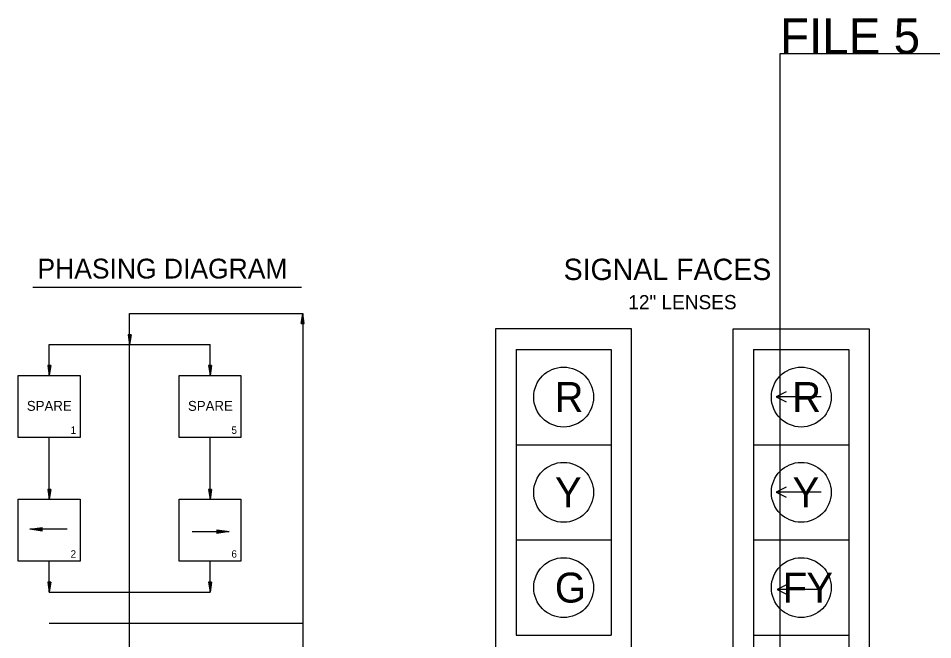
# Model space of a CAD drawing. Extents: x -218554 to 420114, y -565956 to -483460.
# Drawn here: x 418454.1 to 418625.5, y -565580 to -565463.6 of the extents above; entities that cross this region are included whole.
import ezdxf

# ---------------------------------------------------------------- set-up
doc = ezdxf.new("R2010")
doc.units = 0
for name, color, linetype in [('Level 57', 7, 'Continuous'), ('Level 61', 7, 'Continuous'), ('Template', 7, 'Continuous')]:
    doc.layers.add(name, color=color, linetype=linetype)

msp = doc.modelspace()

# ---------------------------------------------------------------- linework, layer by layer
at = {"layer": 'Level 57'}
for p, q in [((418456.77, -565513.98), (418507.17, -565513.98)), ((418474.94, -565640.7), (418474.94, -565518.95)), ((418474.94, -565518.95), (418507.41, -565518.95)), ((418507.13, -565520.81), (418507.41, -565518.95)), ((418507.18, -565520.81), (418507.41, -565519.26)), ((418507.41, -565518.95), (418507.41, -565640.7)), ((418507.69, -565520.81), (418507.41, -565518.95)), ((418507.64, -565520.81), (418507.41, -565519.26)), ((418507.13, -565520.81), (418507.69, -565520.81)), ((418507.23, -565520.81), (418507.41, -565519.58)), ((418507.27, -565520.81), (418507.41, -565519.89)), ((418507.32, -565520.81), (418507.41, -565520.21)), ((418507.37, -565520.81), (418507.41, -565520.52)), ((418507.59, -565520.81), (418507.41, -565519.58)), ((418507.55, -565520.81), (418507.41, -565519.89)), ((418507.5, -565520.81), (418507.41, -565520.21)), ((418507.45, -565520.81), (418507.41, -565520.52)), ((418474.67, -565522.9), (418474.94, -565524.75)), ((418475.22, -565522.9), (418474.67, -565522.9)), ((418474.71, -565522.9), (418474.94, -565524.44)), ((418474.76, -565522.9), (418474.94, -565524.12)), ((418474.81, -565522.9), (418474.94, -565523.81)), ((418474.85, -565522.9), (418474.94, -565523.5)), ((418474.9, -565522.9), (418474.94, -565523.19)), ((418475.22, -565522.9), (418474.94, -565524.75)), ((418475.03, -565522.9), (418474.94, -565523.5)), ((418475.13, -565522.9), (418474.94, -565524.12)), ((418475.18, -565522.9), (418474.94, -565524.44)), ((418475.08, -565522.9), (418474.94, -565523.81)), ((418474.99, -565522.9), (418474.94, -565523.19)), ((418459.87, -565530.55), (418459.87, -565524.75)), ((418459.87, -565524.75), (418490.02, -565524.75)), ((418490.02, -565530.55), (418490.02, -565524.75)), ((418459.59, -565528.69), (418459.87, -565530.55)), ((418460.15, -565528.69), (418459.59, -565528.69)), ((418459.64, -565528.69), (418459.87, -565530.24)), ((418459.69, -565528.69), (418459.87, -565529.92)), ((418459.73, -565528.69), (418459.87, -565529.61)), ((418459.78, -565528.69), (418459.87, -565529.3)), ((418459.83, -565528.69), (418459.87, -565528.99)), ((418460.15, -565528.69), (418459.87, -565530.55)), ((418459.96, -565528.69), (418459.87, -565529.3)), ((418460.05, -565528.69), (418459.87, -565529.92)), ((418460.1, -565528.69), (418459.87, -565530.24)), ((418460.01, -565528.69), (418459.87, -565529.61)), ((418459.91, -565528.69), (418459.87, -565528.99)), ((418489.74, -565528.69), (418490.02, -565530.55)), ((418490.3, -565528.69), (418489.74, -565528.69)), ((418489.79, -565528.69), (418490.02, -565530.24)), ((418489.83, -565528.69), (418490.02, -565529.92)), ((418489.88, -565528.69), (418490.02, -565529.61)), ((418489.93, -565528.69), (418490.02, -565529.3)), ((418489.97, -565528.69), (418490.02, -565528.99)), ((418490.3, -565528.69), (418490.02, -565530.55)), ((418490.11, -565528.69), (418490.02, -565529.3)), ((418490.2, -565528.69), (418490.02, -565529.92)), ((418490.25, -565528.69), (418490.02, -565530.24)), ((418490.16, -565528.69), (418490.02, -565529.61)), ((418490.06, -565528.69), (418490.02, -565528.99)), ((418459.87, -565553.74), (418459.87, -565542.14)), ((418490.02, -565553.74), (418490.02, -565542.14)), ((418459.59, -565551.88), (418459.87, -565553.74)), ((418460.15, -565551.88), (418459.59, -565551.88)), ((418459.64, -565551.88), (418459.87, -565553.43)), ((418459.69, -565551.88), (418459.87, -565553.11)), ((418459.73, -565551.88), (418459.87, -565552.8)), ((418459.78, -565551.88), (418459.87, -565552.49)), ((418459.83, -565551.88), (418459.87, -565552.18)), ((418460.15, -565551.88), (418459.87, -565553.74)), ((418459.96, -565551.88), (418459.87, -565552.49)), ((418460.05, -565551.88), (418459.87, -565553.11)), ((418460.1, -565551.88), (418459.87, -565553.43)), ((418460.01, -565551.88), (418459.87, -565552.8)), ((418459.91, -565551.88), (418459.87, -565552.18)), ((418489.74, -565551.88), (418490.02, -565553.74)), ((418490.3, -565551.88), (418489.74, -565551.88)), ((418489.79, -565551.88), (418490.02, -565553.43)), ((418489.83, -565551.88), (418490.02, -565553.11)), ((418489.88, -565551.88), (418490.02, -565552.8)), ((418489.93, -565551.88), (418490.02, -565552.49)), ((418489.97, -565551.88), (418490.02, -565552.18)), ((418490.3, -565551.88), (418490.02, -565553.74)), ((418490.11, -565551.88), (418490.02, -565552.49)), ((418490.2, -565551.88), (418490.02, -565553.11)), ((418490.25, -565551.88), (418490.02, -565553.43)), ((418490.16, -565551.88), (418490.02, -565552.8)), ((418490.06, -565551.88), (418490.02, -565552.18)), ((418456.26, -565559.36), (418458.58, -565559.01)), ((418463.22, -565559.36), (418456.26, -565559.36)), ((418458.58, -565559.71), (418456.26, -565559.36)), ((418458.58, -565559.07), (418456.65, -565559.36)), ((418456.65, -565559.36), (418458.58, -565559.65)), ((418457.05, -565559.36), (418458.58, -565559.13)), ((418458.58, -565559.59), (418457.05, -565559.36)), ((418458.58, -565559.19), (418457.43, -565559.36)), ((418457.43, -565559.36), (418458.58, -565559.53)), ((418457.83, -565559.36), (418458.58, -565559.25)), ((418458.58, -565559.47), (418457.83, -565559.36)), ((418458.58, -565559.3), (418458.21, -565559.36)), ((418458.21, -565559.36), (418458.58, -565559.41)), ((418458.58, -565559.71), (418458.58, -565559.01)), ((418486.64, -565559.78), (418493.6, -565559.78)), ((418491.28, -565559.43), (418493.6, -565559.78)), ((418491.28, -565559.43), (418491.28, -565560.13)), ((418493.21, -565559.78), (418491.28, -565559.49)), ((418491.28, -565559.55), (418492.82, -565559.78)), ((418492.43, -565559.78), (418491.28, -565559.61)), ((418491.28, -565559.67), (418492.04, -565559.78)), ((418491.65, -565559.78), (418491.28, -565559.73)), ((418493.6, -565559.78), (418491.28, -565560.13)), ((418491.28, -565560.07), (418493.21, -565559.78)), ((418492.82, -565559.78), (418491.28, -565560.01)), ((418491.28, -565559.95), (418492.43, -565559.78)), ((418492.04, -565559.78), (418491.28, -565559.89)), ((418491.28, -565559.84), (418491.65, -565559.78)), ((418459.87, -565571.13), (418459.87, -565565.33)), ((418490.02, -565571.13), (418490.02, -565565.33)), ((418459.59, -565569.28), (418459.87, -565571.13)), ((418460.15, -565569.28), (418459.59, -565569.28)), ((418459.64, -565569.28), (418459.87, -565570.82)), ((418459.69, -565569.28), (418459.87, -565570.5)), ((418459.73, -565569.28), (418459.87, -565570.19)), ((418459.78, -565569.28), (418459.87, -565569.88)), ((418459.83, -565569.28), (418459.87, -565569.57)), ((418460.15, -565569.28), (418459.87, -565571.13)), ((418459.96, -565569.28), (418459.87, -565569.88)), ((418460.05, -565569.28), (418459.87, -565570.5)), ((418460.1, -565569.28), (418459.87, -565570.82)), ((418460.01, -565569.28), (418459.87, -565570.19)), ((418459.91, -565569.28), (418459.87, -565569.57)), ((418489.74, -565569.28), (418490.02, -565571.13)), ((418490.3, -565569.28), (418489.74, -565569.28)), ((418489.79, -565569.28), (418490.02, -565570.82)), ((418489.83, -565569.28), (418490.02, -565570.5)), ((418489.88, -565569.28), (418490.02, -565570.19)), ((418489.93, -565569.28), (418490.02, -565569.88)), ((418489.97, -565569.28), (418490.02, -565569.57)), ((418490.3, -565569.28), (418490.02, -565571.13)), ((418490.11, -565569.28), (418490.02, -565569.88)), ((418490.2, -565569.28), (418490.02, -565570.5)), ((418490.25, -565569.28), (418490.02, -565570.82)), ((418490.16, -565569.28), (418490.02, -565570.19)), ((418490.06, -565569.28), (418490.02, -565569.57)), ((418459.87, -565571.13), (418490.02, -565571.13)), ((418459.87, -565576.93), (418507.41, -565576.93))]:
    msp.add_line(p, q, dxfattribs=at)
for points in [[(418454.07, -565530.55), (418465.67, -565530.55), (418465.67, -565542.14), (418454.07, -565542.14)], [(418484.22, -565530.55), (418495.82, -565530.55), (418495.82, -565542.14), (418484.22, -565542.14)], [(418454.07, -565553.74), (418465.67, -565553.74), (418465.67, -565565.33), (418454.07, -565565.33)], [(418484.22, -565553.74), (418495.82, -565553.74), (418495.82, -565565.33), (418484.22, -565565.33)]]:
    msp.add_lwpolyline(points, close=True, dxfattribs=at)
at = {"layer": 'Level 61'}
for p, q in [((418547.39, -565525.65), (418565.24, -565525.65)), ((418547.39, -565525.65), (418547.39, -565543.5)), ((418565.24, -565525.65), (418565.24, -565543.5)), ((418591.93, -565525.65), (418609.79, -565525.65)), ((418591.93, -565525.65), (418591.93, -565543.5)), ((418609.79, -565525.65), (418609.79, -565543.5)), ((418604.56, -565534.55), (418596.14, -565534.55)), ((418547.39, -565543.5), (418565.24, -565543.5)), ((418547.39, -565543.5), (418547.39, -565561.35)), ((418565.24, -565543.5), (418565.24, -565561.35)), ((418591.93, -565543.5), (418609.79, -565543.5)), ((418591.93, -565543.5), (418591.93, -565561.35)), ((418609.79, -565543.5), (418609.79, -565561.35)), ((418604.56, -565552.4), (418596.14, -565552.4)), ((418547.39, -565561.35), (418565.24, -565561.35)), ((418547.39, -565561.35), (418547.39, -565579.21)), ((418565.24, -565561.35), (418565.24, -565579.21)), ((418591.93, -565561.35), (418609.79, -565561.35)), ((418591.93, -565561.35), (418591.93, -565579.21)), ((418609.79, -565561.35), (418609.79, -565579.21)), ((418604.74, -565570.61), (418596.32, -565570.61)), ((418547.39, -565579.21), (418565.24, -565579.21)), ((418591.93, -565579.21), (418609.79, -565579.21)), ((418591.93, -565579.21), (418591.93, -565597.06)), ((418609.79, -565579.21), (418609.79, -565597.06))]:
    msp.add_line(p, q, dxfattribs=at)
for points in [[(418569.06, -565583.03), (418569.06, -565521.83), (418543.56, -565521.83), (418543.56, -565583.03)], [(418588.11, -565600.88), (418588.11, -565521.83), (418613.61, -565521.83), (418613.61, -565600.88)]]:
    msp.add_lwpolyline(points, close=True, dxfattribs=at)
for points in [[(418598.01, -565533.62), (418596.14, -565534.55), (418598.01, -565535.49)], [(418598.01, -565551.47), (418596.14, -565552.4), (418598.01, -565553.34)], [(418598.19, -565569.67), (418596.32, -565570.61), (418598.19, -565571.54)]]:
    msp.add_lwpolyline(points, dxfattribs=at)
for centre in [(418556.31, -565534.58), (418600.86, -565534.58), (418556.31, -565552.43), (418600.86, -565552.43), (418556.31, -565570.28), (418600.86, -565570.28)]:
    msp.add_circle(centre, 5.61, dxfattribs=at)
at = {"layer": 'Template'}
msp.add_lwpolyline([(418728.86, -565470.29), (418596.87, -565470.29), (418596.87, -565630.35), (418728.86, -565630.35)], close=True, dxfattribs=at)

# ---------------------------------------------------------------- texts
at = {"layer": 'Level 57'}
for s, height, p in [('PHASING DIAGRAM', 3.7104, (418457.67, -565512.37)), ('SPARE', 1.855, (418455.68, -565537.16)), ('SPARE', 1.855, (418485.88, -565537.16)), ('1', 1.39, (418463.88, -565541.48)), ('5', 1.39, (418494.03, -565541.48)), ('2', 1.39, (418463.88, -565564.67)), ('6', 1.39, (418494.03, -565564.67))]:
    msp.add_text(s, height=height, rotation=360, dxfattribs=at).set_placement(p)
at = {"layer": 'Level 61'}
for s, height, p in [('SIGNAL FACES', 4, (418556.3, -565512.66)), ('R', 5.61, (418554.61, -565537.38)), ('R', 5.61, (418599.16, -565537.38)), ('Y', 5.61, (418554.68, -565555.23)), ('Y', 5.61, (418599.23, -565555.23)), ('G', 5.61, (418554.66, -565573.08)), ('F', 5.61, (418597.39, -565573.08)), ('Y', 5.61, (418601.81, -565573.08))]:
    msp.add_text(s, height=height, dxfattribs=at).set_placement(p)
msp.add_text('12" LENSES', height=2.667, rotation=0.072, dxfattribs=at).set_placement((418568.44, -565518.15))
at = {"layer": 'Template'}
msp.add_text('FILE 5', height=6.667, rotation=360, dxfattribs=at).set_placement((418596.87, -565470.29))

doc.saveas('drawing.dxf')
